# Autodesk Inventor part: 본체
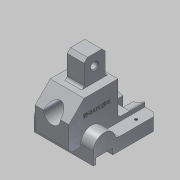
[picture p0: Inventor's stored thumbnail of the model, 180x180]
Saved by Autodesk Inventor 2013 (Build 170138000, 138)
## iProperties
Created: 2016-11
Part Number: 본체
Material: 알루미늄 6061
Document SubType Name: Modeling
Designer: Administrator
Density: 2.71 g/cm^3
Mass: 472.114 g
Surface Area: 320.727 cm^2
Volume: 174.212 cm^3
Author: Administrator
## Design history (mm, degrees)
sketch "스케치1"
  geometry: L1 (-35, 38)-(35, 38); L2 (35, 38)-(35, -38); L3 (35, -38)-(-35, -38); L4 (-35, -38)-(-35, 38); L5 (-35, 38)-(35, -38); L6 (35, 38)-(-35, -38); 1 further point
  constraints: 12 end point, 2 midpoint, 2 parallel, 1 horizontal, 1 perpendicular
  dimensions: "d0" = 76 distance of L1.end L2.end; "d2" = 70 distance of L1.start L1.end
extrude "돌출1" new body sketch "스케치1" distance "d3" = 15; taper "d4" = 0 deg
sketch "스케치2"
  geometry: L1 (35, 38)-(-35, 38) reference; L2 (35, -38)-(35, 38) reference; L3 (-20, 6)-(20, 6); L4 (20, 6)-(20, -52); L5 (20, -52)-(-20, -52); L6 (-20, -52)-(-20, 6); 1 further point
  constraints: 8 end point, 2 parallel, 1 horizontal, 1 perpendicular
  dimensions: "d5" = 90 distance between parallel lines of L1 L5; "d6" = 58 distance of L5.end L3.start; "d7" = 40 distance of L4.end L5.end; "d9" = 15 distance between parallel lines of L2 L4
extrude "돌출2" join sketch "스케치2" distance "d10" = 27; taper "d11" = 0 deg
sketch "스케치3"
  geometry: L1 (38, 15)-(38, 0) reference; L2 (38, 0)-(-38, 0) reference; L3 (-38, 0)-(-38, 15) reference; L4 (-38, 15)-(-52, 15) reference; L5 (-52, 15)-(-52, 42) reference; L6 (-52, 42)-(6, 42) reference; L7 (6, 42)-(6, 15) reference; L8 (6, 15)-(38, 15) reference; L9 (-52, 42)-(-34, 60); L10 (-34, 60)-(6, 60); L11 (6, 60)-(6, 42); 1 further point
  constraints: 6 end point, 1 collinear, 1 perpendicular, 1 point on line
  dimensions: "d12" = 45 deg angle of L10 L9; "d13" = 18 distance from line of L5 L9.end
extrude "돌출3" join sketch "스케치3" stored distance "d14" = 40; taper "d15" = 0 deg
sketch "스케치4"
  geometry: L1 (38, 15)-(38, 0) reference; L2 (38, 0)-(-38, 0) reference; L3 (-38, 0)-(-38, 15) reference; L4 (-38, 15)-(-52, 15) reference; L5 (-52, 15)-(-52, 42) reference; L6 (-52, 42)-(-34, 60) reference; L7 (-34, 60)-(6, 60) reference; L8 (6, 60)-(6, 15) reference; L9 (6, 15)-(38, 15) reference; L10 (-24, 60)-(-24, 90); L11 (-24, 90)-(1, 90); L12 (1, 90)-(1, 60); 1 further point
  constraints: 6 end point, 3 perpendicular, 2 point on line
  dimensions: "d16" = 25 distance of L10.end L11.end; "d18" = 5 distance between parallel lines of L12 L8; "d19" = 90 distance between parallel lines of L11 L2
extrude "돌출4" join sketch "스케치4" stored distance "d20" = 20; taper "d21" = 0 deg
chamfer "모따기1" distance "d22" = 4; stored, may be unused: second distance "d23" = 2, angle "d24" = 45 deg
sketch "스케치5"
  geometry: L1 (0, 76)-(0, 0) reference; L2 (0, 0)-(-15, 0) reference; L3 (0, 3)-(-7, 3); L4 (-7, 3)-(-7, 23); L5 (-7, 23)-(0, 23); 1 further point
  constraints: 6 end point, 2 perpendicular, 2 point on line, 1 parallel
  dimensions: "d27" = 20 distance of L3.end L4.end; "d29" = 3 distance between parallel lines of L2 L3; "d30" = 7 distance of L3.start L3.end
extrude "돌출5" cut sketch "스케치5" stored distance "d31" = 20; taper "d32" = 0 deg
sketch "스케치6"
  geometry: L1 (15, 76)-(0, 76) reference; L2 (0, 0)-(0, 76) reference; A1 r 13 centre (0, 13) between (0, 26) and (0, 0); 1 further point
  constraints: 3 point on line, 2 point on circle, 1 centre point
  dimensions: "d33" = 63 distance from line of L1 A1.centre; "d34" = 13 radius of A1
extrude "돌출6" join sketch "스케치6" stored distance "d35" = 20; taper "d36" = 0 deg
sketch "스케치7"
  geometry: L1 (0, 76)-(0, 0) reference; L2 (-15, 76)-(0, 76) reference; A1 r 13 centre (0, 13) between (0, 0) and (0, 26); 1 further point
  constraints: 3 point on line, 2 point on circle, 1 centre point
  dimensions: "d37" = 63 distance from line of L2 A1.centre; "d38" = 13 radius of A1
extrude "돌출7" join sketch "스케치7" stored distance "d39" = 20; taper "d40" = 0 deg
sketch "스케치8"
  geometry: L1 (-52, 42)-(-34, 60) reference; L2 (-34, 60)-(-24, 60) reference; L3 (-24, 60)-(-24, 86) reference; L4 (-24, 86)-(-20, 90) reference; L5 (-20, 90)-(-3, 90) reference; L6 (-3, 90)-(1, 86) reference; L7 (1, 86)-(1, 60) reference; L8 (1, 60)-(6, 60) reference; L9 (6, 60)-(6, 15) reference; L10 (6, 15)-(38, 15) reference; L11 (38, 15)-(38, 0) reference; L12 (38, 0)-(-15, 0) reference; L13 (-15, 0)-(-15, 7) reference; L14 (-15, 7)-(-35, 7) reference; L15 (-35, 7)-(-35, 0) reference; L16 (-35, 0)-(-38, 0) reference; L17 (-38, 0)-(-38, 15) reference; L18 (-38, 15)-(-52, 15) reference; L19 (-52, 15)-(-52, 42) reference; L20 (38, 15)-(38, 20); L21 (38, 20)-(6, 20); 1 further point
  constraints: 4 end point, 1 parallel, 1 perpendicular, 1 point on line
  dimensions: "d41" = 5 distance of L10.end L20.end
extrude "돌출8" join sketch "스케치8" stored distance "d42" = 40; taper "d43" = 0 deg
sketch "스케치9"
  geometry: L1 (-15, 60)-(55, 60) reference; C1 r 14.5 at (20, 18); 2 further points
  constraints: 1 centre point, 1 midpoint, 1 vertical alignment
  dimensions: "d44" = 42 distance from line of L1 C1.centre; "d45" = 29 diameter of C1
extrude "돌출9" cut sketch "스케치9" distance "d46" = 7; taper "d47" = 0 deg
sketch "스케치10"
  geometry: C1 r 14.5 at (0, 0) reference; C2 r 10 at (0, 0); 1 further point
  constraints: 1 centre point, 1 coincident
  dimensions: "d48" = 20 diameter of C2
extrude "돌출10" cut sketch "스케치10" stored distance "d50" = 7; taper "d51" = 0 deg
sketch "스케치11"
  geometry: L1 (-86, -24)-(-60, -24) reference; L2 (0, 38)-(0, -15) reference; C1 r 4 at (-77, -11.5); 1 further point
  constraints: 1 centre point
  dimensions: "d52" = 12.5 distance from line of L1 C1.centre; "d53" = 77 distance from line of L2 C1.centre; "d54" = 8 diameter of C1
extrude "돌출11" cut sketch "스케치11" stored distance "d55" = 7; taper "d56" = 0 deg
sketch "스케치12"
  geometry: L1 (0, 0)-(70, 0) reference; L2 (15, -20)-(55, -20) reference; L3 (29, -13.627)-(29, 0); L4 (41, -13.627)-(41, 0); C1 r 14.5 at (35, -42) reference; A1 r 29 centre (35, -42) between (53.894, -20) and (41, -13.627); A2 r 29 centre (35, -42) between (29, -13.627) and (16.106, -20); 1 further point
  constraints: 4 end point, 4 point on circle, 4 point on line, 2 centre point, 2 perpendicular, 1 coincident, 1 parallel
  dimensions: "d59" = 12 distance between parallel lines of L4 L3; "d60" = 29 radius of A1; "d61" = 29 radius of A2
extrude "돌출12" cut sketch "스케치12" distance "d62" = 18; taper "d63" = 0 deg
fillet "모깎기1" dims "d64" = 3
chamfer "모따기3" distance "d68" = 1; stored, may be unused: second distance "d69" = 2, angle "d70" = 45 deg
chamfer "모따기4" distance "d71" = 1; stored, may be unused: second distance "d72" = 2, angle "d73" = 45 deg
chamfer "모따기5" distance "d74" = 5; stored, may be unused: second distance "d75" = 2, angle "d76" = 45 deg
fillet "모깎기2" dims "d77" = 5
sketch "스케치13"
  geometry: L1 (37, 40)-(0, 40) reference; L2 (0, 40)-(0, 0) reference; L3 (15.132, -4.239)-(15.132, 34.239); L4 (15.132, 34.239)-(20.868, 34.239); L5 (20.868, 34.239)-(20.868, -4.239); L6 (20.868, -4.239)-(15.132, -4.239); L7 (18, -4.239)-(18, 34.239); L8 (20.868, 15)-(15.132, 15); 1 further point
  constraints: 4 end point, 4 midpoint, 2 other
  dimensions: "d78" = 18 distance between parallel lines of L2 L7; "d79" = 25 distance between parallel lines of L1 L8
feature "엠보싱1" sketch "스케치13" dims "d0" = 76, "d2" = 70, "d80" = 0.5, "d81" = 0
sketch "스케치14"
  geometry: L1 (30, 38)-(20, 38) reference; L2 (20, 38)-(20, -7.708) reference; L3 (27.5, 38)-(27.5, 20); L4 (18.894, 20)-(-18.894, 20) reference; L5 (0, 20)-(0, 37.847); 1 further point
  constraints: 4 end point, 1 midpoint, 1 parallel, 1 perpendicular, 1 point on line
  dimensions: "d82" = 18 distance of L3.start L3.end; "d84" = 55 diameter of L3 L5
hole "구멍1" sketch "스케치14" at (27.5, 20) diameter "d85" = 3.242; stored, may be unused: countersink angle "d89" = 90 deg, drill point angle "d91" = 118 deg; dims "d86" = 6, "d87" = 4, "d88" = 2, "d90" = 8
sketch "스케치15"
  geometry: L1 (-20, 38)-(-30, 38) reference; L2 (-35, 33)-(-35, -7.708) reference; L3 (-27.5, 38)-(-27.5, 20); C1 r 1.621 at (27.5, 20) reference; 1 further point
  constraints: 2 end point, 1 parallel, 1 point on line
  dimensions: "d92" = 18 distance of L3.start L3.end; "d94" = 55 distance from line of L3 C1.centre
hole "구멍2" sketch "스케치15" at (-27.5, 20) diameter "d95" = 3.242; stored, may be unused: countersink angle "d99" = 90 deg, drill point angle "d101" = 118 deg; dims "d96" = 6, "d97" = 4, "d98" = 2, "d100" = 8
sketch "스케치16"
  geometry: L1 (20, -38)-(-20, -38) reference; L2 (-20, -38)-(-20, -52) reference; L3 (-20, -52)-(20, -52) reference; L4 (20, -52)-(20, -38) reference; 1 further point
extrude "돌출13" join sketch "스케치16" distance "d102" = 3; taper "d103" = 0 deg
chamfer "모따기6" distance "d104" = 4; stored, may be unused: second distance "d105" = 2, angle "d106" = 45 deg
node "솔리드1"
node "절단 모서리 투영1"
node "절단 모서리 투영2"
node "절단 모서리 투영3"
other parameters: "d57" = 29
